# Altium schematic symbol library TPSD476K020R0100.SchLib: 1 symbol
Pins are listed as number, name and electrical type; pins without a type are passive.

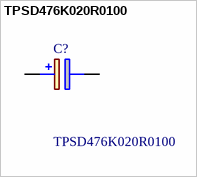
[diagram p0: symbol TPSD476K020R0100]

## TPSD476K020R0100
designator C?
AVX Tantalum Capacitor 47uF 20V dc Electrolytic Solid TPS Series; Geometry.Height: 3.1mm
footprint CAPPM7344X310N
pins: 1 +, 2 -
